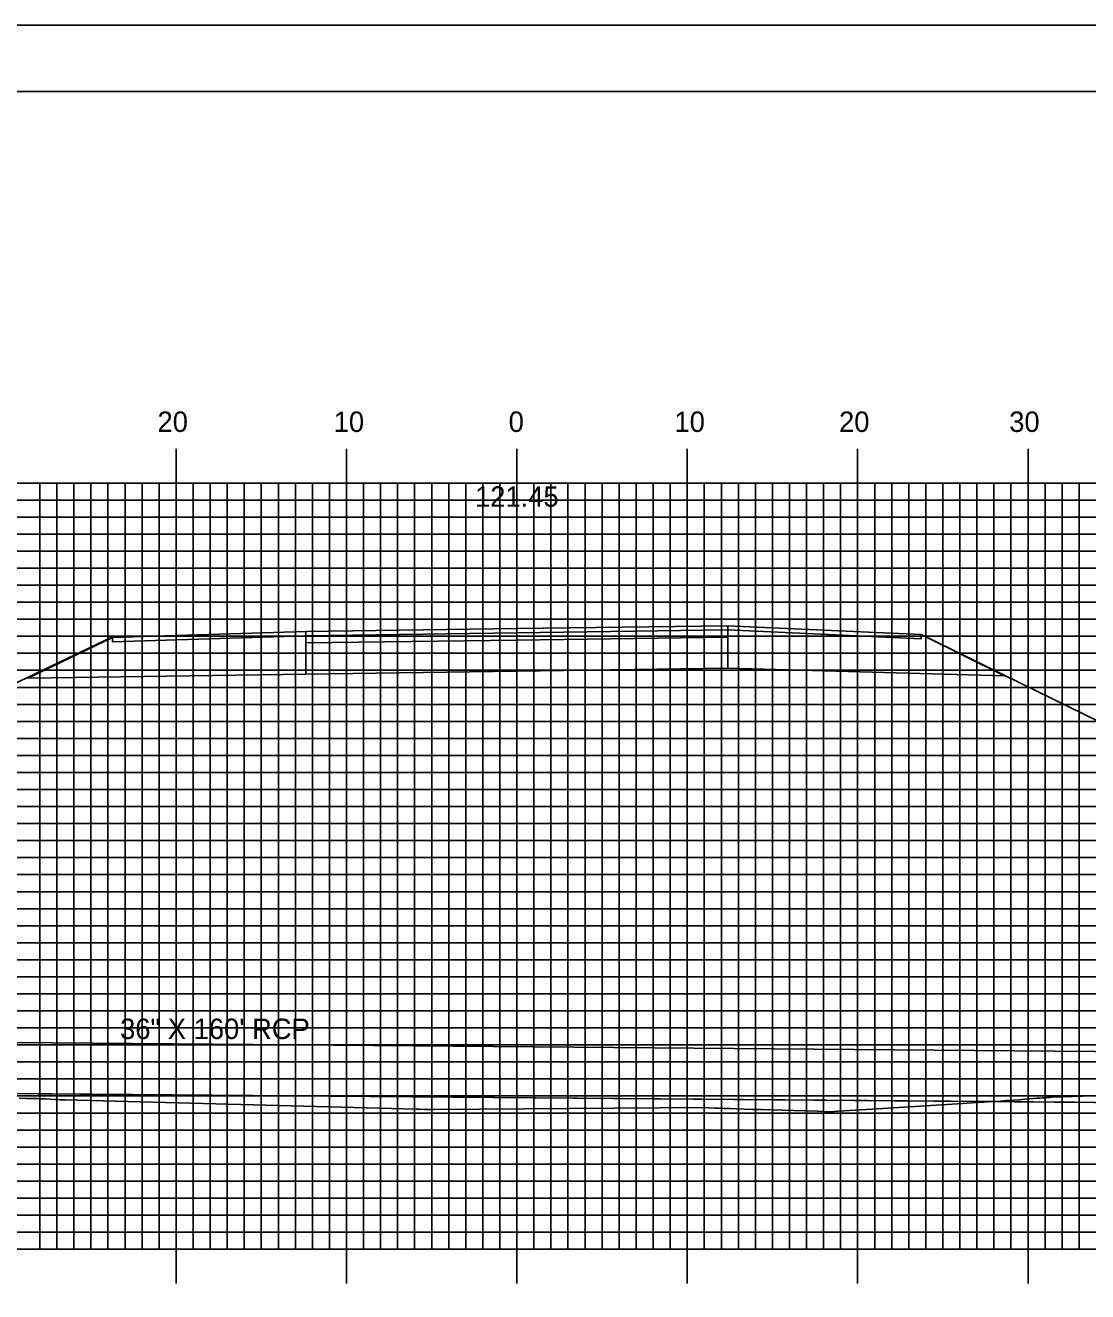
# Model space of a CAD drawing. Extents: x 1785795 to 1786139, y 442591 to 442811.
# Drawn here: x 1785932.2 to 1785994.6, y 442736.2 to 442810.5 of the extents above; entities that cross this region are included whole.
import ezdxf

# ---------------------------------------------------------------- set-up
doc = ezdxf.new("R2010")
doc.units = 0
for name, color, linetype in [('BORDER', 7, 'Continuous'), ('D_Drainage_Culvert', 7, 'Continuous'), ('D_Drainage_Text', 7, 'Continuous'), ('D_Roadway_Centerline_Text', 7, 'Continuous'), ('D_Roadway_Edge_Shoulder', 7, 'Continuous'), ('D_Roadway_Edge_TW', 7, 'Continuous'), ('D_Roadway_Pavement', 7, 'Continuous'), ('D_Roadway_SlopeLines', 7, 'Continuous'), ('D_Roadway_SubGrade', 7, 'Continuous'), ('H_V ANNOTATION', 7, 'Continuous'), ('MAJOR', 7, 'Continuous'), ('MINOR', 7, 'Continuous'), ('PLOT BOUNDARY', 7, 'Continuous'), ('S_Roadway_Centerline', 7, 'Continuous')]:
    doc.layers.add(name, color=color, linetype=linetype)

msp = doc.modelspace()

# ---------------------------------------------------------------- linework, layer by layer
at = {"layer": 'BORDER'}
msp.add_lwpolyline([(1785811.452, 442596.665), (1786131.452, 442596.665), (1786131.452, 442806.665), (1785811.452, 442806.665)], close=True, dxfattribs=at)
at = {"layer": 'D_Drainage_Culvert'}
for p, q in [((1785958.558, 442748.686), (1785963.545, 442748.645)), ((1785882.012, 442748.221), (1786041.684, 442746.896))]:
    msp.add_line(p, q, dxfattribs=at)
msp.add_lwpolyline([(1785882.012, 442748.221), (1785882.037, 442751.221), (1786042.031, 442749.893), (1786042.006, 442746.893)], close=True, dxfattribs=at)
at = {"layer": 'D_Roadway_Edge_Shoulder'}
for points in [[(1785948.672, 442774.94), (1785940.418, 442774.681), (1785940.418, 442774.681), (1785937.323, 442774.584), (1785937.323, 442774.334), (1785948.672, 442774.69)], [(1785973.43, 442775.285), (1785981.681, 442774.905), (1785981.681, 442774.905), (1785984.776, 442774.762), (1785984.776, 442774.512), (1785973.43, 442775.035)]]:
    msp.add_lwpolyline(points, close=True, dxfattribs=at)
at = {"layer": 'D_Roadway_Edge_TW'}
msp.add_lwpolyline([(1785948.672, 442774.69), (1785948.672, 442774.94), (1785961.052, 442775.112), (1785973.43, 442775.285), (1785973.43, 442775.035), (1785961.052, 442774.862)], close=True, dxfattribs=at)
at = {"layer": 'D_Roadway_Pavement'}
msp.add_lwpolyline([(1785948.672, 442774.273), (1785948.672, 442774.69), (1785961.052, 442774.862), (1785973.43, 442775.035), (1785973.43, 442774.619), (1785961.052, 442774.446)], close=True, dxfattribs=at)
for points in [[(1785948.672, 442774.69), (1785948.672, 442774.273)], [(1785973.43, 442775.035), (1785973.43, 442774.619)]]:
    msp.add_lwpolyline(points, dxfattribs=at)
at = {"layer": 'D_Roadway_SlopeLines'}
for p, q in [((1785937.323, 442774.633), (1785888.966, 442751.54)), ((1785984.776, 442774.762), (1786034.712, 442750.321))]:
    msp.add_line(p, q, dxfattribs=at)
at = {"layer": 'D_Roadway_SubGrade'}
for points in [[(1785948.672, 442774.273), (1785948.672, 442774.69), (1785937.323, 442774.334), (1785937.323, 442774.584), (1785932.353, 442772.213), (1785948.672, 442772.44)], [(1785948.672, 442772.44), (1785948.672, 442774.69), (1785948.672, 442774.273), (1785961.052, 442774.446), (1785973.43, 442774.619), (1785973.43, 442775.035), (1785973.43, 442772.785), (1785961.052, 442772.612)], [(1785973.43, 442774.619), (1785973.43, 442775.035), (1785984.776, 442774.512), (1785984.776, 442774.762), (1785989.674, 442772.351), (1785973.43, 442772.785)]]:
    msp.add_lwpolyline(points, close=True, dxfattribs=at)
at = {"layer": 'MAJOR'}
for p, q in [((1785941.052, 442785.669), (1785941.052, 442783.665)), ((1785951.052, 442785.669), (1785951.052, 442783.665)), ((1785961.052, 442785.669), (1785961.052, 442783.665)), ((1785971.052, 442785.669), (1785971.052, 442783.665)), ((1785981.052, 442785.669), (1785981.052, 442783.665)), ((1785991.052, 442785.669), (1785991.052, 442783.665)), ((1785821.052, 442783.665), (1786101.052, 442783.665)), ((1785821.052, 442783.665), (1786101.052, 442783.665)), ((1785941.052, 442738.665), (1785941.052, 442783.665)), ((1785951.052, 442738.665), (1785951.052, 442783.665)), ((1785961.052, 442738.665), (1785961.052, 442783.665)), ((1785971.052, 442738.665), (1785971.052, 442783.665)), ((1785981.052, 442738.665), (1785981.052, 442783.665)), ((1785991.052, 442738.665), (1785991.052, 442783.665)), ((1785821.052, 442778.665), (1786101.052, 442778.665)), ((1785821.052, 442773.665), (1786101.052, 442773.665)), ((1785821.052, 442768.665), (1786101.052, 442768.665)), ((1785821.052, 442763.665), (1786101.052, 442763.665)), ((1785821.052, 442758.665), (1786101.052, 442758.665)), ((1785821.052, 442753.665), (1786101.052, 442753.665)), ((1785821.052, 442748.665), (1786101.052, 442748.665)), ((1785821.052, 442743.665), (1786101.052, 442743.665)), ((1785821.052, 442738.665), (1786101.052, 442738.665)), ((1785821.052, 442738.665), (1786101.052, 442738.665)), ((1785941.052, 442736.661), (1785941.052, 442738.665)), ((1785951.052, 442736.661), (1785951.052, 442738.665)), ((1785961.052, 442736.661), (1785961.052, 442738.665)), ((1785971.052, 442736.661), (1785971.052, 442738.665)), ((1785981.052, 442736.661), (1785981.052, 442738.665)), ((1785991.052, 442736.661), (1785991.052, 442738.665))]:
    msp.add_line(p, q, dxfattribs=at)
at = {"layer": 'MINOR'}
for p, q in [((1785933.052, 442738.665), (1785933.052, 442783.665)), ((1785934.052, 442738.665), (1785934.052, 442783.665)), ((1785935.052, 442738.665), (1785935.052, 442783.665)), ((1785936.052, 442738.665), (1785936.052, 442783.665)), ((1785937.052, 442738.665), (1785937.052, 442783.665)), ((1785938.052, 442738.665), (1785938.052, 442783.665)), ((1785939.052, 442738.665), (1785939.052, 442783.665)), ((1785940.052, 442738.665), (1785940.052, 442783.665)), ((1785942.052, 442738.665), (1785942.052, 442783.665)), ((1785943.052, 442738.665), (1785943.052, 442783.665)), ((1785944.052, 442738.665), (1785944.052, 442783.665)), ((1785945.052, 442738.665), (1785945.052, 442783.665)), ((1785946.052, 442738.665), (1785946.052, 442783.665)), ((1785947.052, 442738.665), (1785947.052, 442783.665)), ((1785948.052, 442738.665), (1785948.052, 442783.665)), ((1785949.052, 442738.665), (1785949.052, 442783.665)), ((1785950.052, 442738.665), (1785950.052, 442783.665)), ((1785952.052, 442738.665), (1785952.052, 442783.665)), ((1785953.052, 442738.665), (1785953.052, 442783.665)), ((1785954.052, 442738.665), (1785954.052, 442783.665)), ((1785955.052, 442738.665), (1785955.052, 442783.665)), ((1785956.052, 442738.665), (1785956.052, 442783.665)), ((1785957.052, 442738.665), (1785957.052, 442783.665)), ((1785958.052, 442738.665), (1785958.052, 442783.665)), ((1785959.052, 442738.665), (1785959.052, 442783.665)), ((1785960.052, 442738.665), (1785960.052, 442783.665)), ((1785962.052, 442738.665), (1785962.052, 442783.665)), ((1785963.052, 442738.665), (1785963.052, 442783.665)), ((1785964.052, 442738.665), (1785964.052, 442783.665)), ((1785965.052, 442738.665), (1785965.052, 442783.665)), ((1785966.052, 442738.665), (1785966.052, 442783.665)), ((1785967.052, 442738.665), (1785967.052, 442783.665)), ((1785968.052, 442738.665), (1785968.052, 442783.665)), ((1785969.052, 442738.665), (1785969.052, 442783.665)), ((1785970.052, 442738.665), (1785970.052, 442783.665)), ((1785972.052, 442738.665), (1785972.052, 442783.665)), ((1785973.052, 442738.665), (1785973.052, 442783.665)), ((1785974.052, 442738.665), (1785974.052, 442783.665)), ((1785975.052, 442738.665), (1785975.052, 442783.665)), ((1785976.052, 442738.665), (1785976.052, 442783.665)), ((1785977.052, 442738.665), (1785977.052, 442783.665)), ((1785978.052, 442738.665), (1785978.052, 442783.665)), ((1785979.052, 442738.665), (1785979.052, 442783.665)), ((1785980.052, 442738.665), (1785980.052, 442783.665)), ((1785982.052, 442738.665), (1785982.052, 442783.665)), ((1785983.052, 442738.665), (1785983.052, 442783.665)), ((1785984.052, 442738.665), (1785984.052, 442783.665)), ((1785985.052, 442738.665), (1785985.052, 442783.665)), ((1785986.052, 442738.665), (1785986.052, 442783.665)), ((1785987.052, 442738.665), (1785987.052, 442783.665)), ((1785988.052, 442738.665), (1785988.052, 442783.665)), ((1785989.052, 442738.665), (1785989.052, 442783.665)), ((1785990.052, 442738.665), (1785990.052, 442783.665)), ((1785992.052, 442738.665), (1785992.052, 442783.665)), ((1785993.052, 442738.665), (1785993.052, 442783.665)), ((1785994.052, 442738.665), (1785994.052, 442783.665)), ((1785821.052, 442782.665), (1786101.052, 442782.665)), ((1785821.052, 442781.665), (1786101.052, 442781.665)), ((1785821.052, 442780.665), (1786101.052, 442780.665)), ((1785821.052, 442779.665), (1786101.052, 442779.665)), ((1785821.052, 442777.665), (1786101.052, 442777.665)), ((1785821.052, 442776.665), (1786101.052, 442776.665)), ((1785821.052, 442775.665), (1786101.052, 442775.665)), ((1785821.052, 442774.665), (1786101.052, 442774.665)), ((1785821.052, 442772.665), (1786101.052, 442772.665)), ((1785821.052, 442771.665), (1786101.052, 442771.665)), ((1785821.052, 442770.665), (1786101.052, 442770.665)), ((1785821.052, 442769.665), (1786101.052, 442769.665)), ((1785821.052, 442767.665), (1786101.052, 442767.665)), ((1785821.052, 442766.665), (1786101.052, 442766.665)), ((1785821.052, 442765.665), (1786101.052, 442765.665)), ((1785821.052, 442764.665), (1786101.052, 442764.665)), ((1785821.052, 442762.665), (1786101.052, 442762.665)), ((1785821.052, 442761.665), (1786101.052, 442761.665)), ((1785821.052, 442760.665), (1786101.052, 442760.665)), ((1785821.052, 442759.665), (1786101.052, 442759.665)), ((1785821.052, 442757.665), (1786101.052, 442757.665)), ((1785821.052, 442756.665), (1786101.052, 442756.665)), ((1785821.052, 442755.665), (1786101.052, 442755.665)), ((1785821.052, 442754.665), (1786101.052, 442754.665)), ((1785821.052, 442752.665), (1786101.052, 442752.665)), ((1785821.052, 442751.665), (1786101.052, 442751.665)), ((1785821.052, 442750.665), (1786101.052, 442750.665)), ((1785821.052, 442749.665), (1786101.052, 442749.665)), ((1785821.052, 442747.665), (1786101.052, 442747.665)), ((1785821.052, 442746.665), (1786101.052, 442746.665)), ((1785821.052, 442745.665), (1786101.052, 442745.665)), ((1785821.052, 442744.665), (1786101.052, 442744.665)), ((1785821.052, 442742.665), (1786101.052, 442742.665)), ((1785821.052, 442741.665), (1786101.052, 442741.665)), ((1785821.052, 442740.665), (1786101.052, 442740.665)), ((1785821.052, 442739.665), (1786101.052, 442739.665))]:
    msp.add_line(p, q, dxfattribs=at)
at = {"layer": 'PLOT BOUNDARY'}
msp.add_lwpolyline([(1785795.265, 442590.547), (1786135.265, 442590.547), (1786135.265, 442810.547), (1785795.265, 442810.547)], close=True, dxfattribs=at)
at = {"layer": 'S_Roadway_Centerline'}
msp.add_lwpolyline([(1785931.845, 442747.534), (1785932.235, 442747.526), (1785932.589, 442747.517), (1785932.904, 442747.509), (1785933.054, 442747.504), (1785933.216, 442747.497), (1785933.387, 442747.49), (1785933.919, 442747.464), (1785934.091, 442747.455), (1785934.255, 442747.448), (1785934.407, 442747.442), (1785934.545, 442747.437), (1785955.166, 442746.888), (1785955.179, 442746.888), (1785955.19, 442746.888), (1785955.202, 442746.888), (1785955.214, 442746.888), (1785955.226, 442746.888), (1785955.239, 442746.888), (1785955.251, 442746.888), (1785955.263, 442746.888), (1785955.274, 442746.888), (1785955.284, 442746.888), (1785955.293, 442746.888), (1785955.302, 442746.888), (1785955.31, 442746.888), (1785955.319, 442746.888), (1785955.327, 442746.887), (1785955.641, 442746.881), (1785956.02, 442746.877), (1785956.05, 442746.876), (1785956.084, 442746.876), (1785956.122, 442746.876), (1785956.164, 442746.875), (1785956.21, 442746.874), (1785972.079, 442746.982), (1785972.281, 442746.972), (1785972.683, 442746.953), (1785972.933, 442746.943), (1785973.226, 442746.932), (1785973.565, 442746.921), (1785973.951, 442746.909), (1785974.387, 442746.895), (1785974.875, 442746.881), (1785975.415, 442746.865), (1785976.004, 442746.848), (1785976.639, 442746.829), (1785977.309, 442746.809), (1785977.998, 442746.788), (1785978.711, 442746.765), (1785979.421, 442746.744), (1785979.934, 442746.776), (1785982.53, 442746.939), (1785984.41, 442747.055), (1785986.911, 442747.21), (1785987.767, 442747.263), (1785988.448, 442747.306), (1785988.995, 442747.341), (1785989.434, 442747.369), (1785989.786, 442747.394), (1785990.191, 442747.423), (1785990.553, 442747.449), (1785990.869, 442747.473), (1785991.141, 442747.494), (1785991.374, 442747.512), (1785991.572, 442747.528), (1785991.741, 442747.541), (1785991.884, 442747.552), (1785992.006, 442747.562), (1785992.11, 442747.57), (1785992.198, 442747.576), (1785992.266, 442747.581), (1785992.335, 442747.586), (1785992.403, 442747.591), (1785992.469, 442747.595), (1785997.797, 442747.781)], dxfattribs=at)

# ---------------------------------------------------------------- texts
at = {"layer": 'D_Drainage_Text'}
msp.add_text('36" X 160\' RCP', height=1.2, dxfattribs=at).set_placement((1785937.763, 442751.009))
at = {"layer": 'D_Roadway_Centerline_Text'}
msp.add_text('121.45', height=1.2, dxfattribs=at).set_placement((1785958.596, 442782.272))
at = {"layer": 'H_V ANNOTATION'}
for s, p in [('20', (1785939.96, 442786.665)), ('10', (1785950.302, 442786.665)), ('0', (1785960.57, 442786.665)), ('10', (1785970.302, 442786.665)), ('20', (1785979.96, 442786.665)), ('30', (1785989.949, 442786.665))]:
    msp.add_text(s, height=1.2, dxfattribs=at).set_placement(p)

doc.saveas('drawing.dxf')
